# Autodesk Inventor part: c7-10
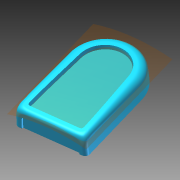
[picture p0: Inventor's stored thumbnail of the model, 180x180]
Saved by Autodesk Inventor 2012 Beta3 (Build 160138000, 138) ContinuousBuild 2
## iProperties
Created: 2010-12
Part Number: c7-10
Material: Default
Document SubType Name: Modeling
Designer: Beta-8540w
Density: 1 g/cm^3
Author: Beta-8540w
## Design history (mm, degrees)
sketch "Sketch1"
  geometry: L1 (-25, 0)-(25, 0); L2 (25, 0)-(25, 80); L3 (25, 80)-(-25, 80); L4 (-25, 80)-(-25, 0); 2 further points
  constraints: 8 end point, 2 parallel, 1 coincident, 1 horizontal, 1 midpoint, 1 perpendicular
  dimensions: "d0" = 50 distance of L3.end L2.end; "d1" = 80 distance of L2.end L1.end
extrude "Extrusion1" new body sketch "Sketch1" distance "d2" = 15; taper "d3" = 0 deg
feature "FaceDraft1" dims angle "d4" = -2 deg
fillet "Fillet1"
fillet "Fillet2" dims "d5" = 8, "d6" = 8, "d7" = 8, "d8" = 8, "d9" = 8, "d10" = 8, "d11" = 3, "d12" = 3, "d13" = 3, "d14" = 6, "d15" = 5
sketch "Sketch2"
  geometry: L1 (5.522, 12)-(38.474, 12) reference; L2 (0, 0)-(43.996, 0) reference; L3 (41.757, 6.83)-(41.995, 0); L4 (41.925, 2)-(2.071, 2); L5 (2.001, 0)-(2.24, 6.83); L6 (5.522, 10)-(38.474, 10); A1 r 5.284 centre (38.474, 6.716) between (43.755, 6.9) and (38.474, 12) reference; A2 r 5.284 centre (5.522, 6.716) between (5.522, 12) and (0.241, 6.9) reference; A3 r 3.284 centre (38.474, 6.716) between (41.757, 6.83) and (38.474, 10); A4 r 3.284 centre (5.522, 6.716) between (5.522, 10) and (2.24, 6.83); 1 further point
  constraints: 8 end point, 4 point on circle, 4 point on line, 2 centre point, 1 other
  dimensions: "d16" = 2 radial gap between concentric circles of A2 A4
extrude "Extrusion2" cut sketch "Sketch2" distance "d17" = 1; taper "d18" = 0 deg
feature "FaceDraft2" dims angle "d19" = 15 deg
sketch "Sketch3" dims "d20" = 2.5
  geometry: L1 (16.476, 3)-(-16.476, 3) reference; L2 (16.476, 5.5)-(-16.476, 5.5); 9 further points
  constraints: 2 end point, 2 parallel, 1 horizontal alignment, 19 other
extrude "Extrusion3" cut sketch "Sketch3" distance "d21" = 3; taper "d22" = 0 deg
feature "FaceDraft3" dims angle "d23" = 10 deg
workplane "Work Plane1"
sketch "Sketch4"
  geometry: L1 (41.1, -1.222)-(41.476, -12) reference; L2 (41.476, -12)-(-8.524, -12) reference; L3 (-8.524, -12)-(-8.147, -1.222) reference; L4 (-3.776, 3)-(-1.272, 3) reference; L5 (-0.743, 0)-(33.695, 0) reference; L6 (34.225, 3)-(36.728, 3) reference; L7 (-11.024, -1.856)-(43.976, -1.856); A1 r 100 centre (16.476, -98) between (43.976, -1.856) and (-11.024, -1.856); 2 further points
  constraints: 2 end point, 2 point on circle, 1 centre point, 1 midpoint, 1 parallel, 1 vertical alignment, 4 other
  dimensions: "d25" = 100 radius of A1; "d26" = 14 distance edge to line of A1 L2; "d27" = 55 distance of L7.start L7.end
extrude_surface "ExtrusionSrf1" sketch "Sketch4" dims "d28" = 86, "d29" = 0
body "Solid1"
body "Srf1"
node "Project Cut Edges1"
